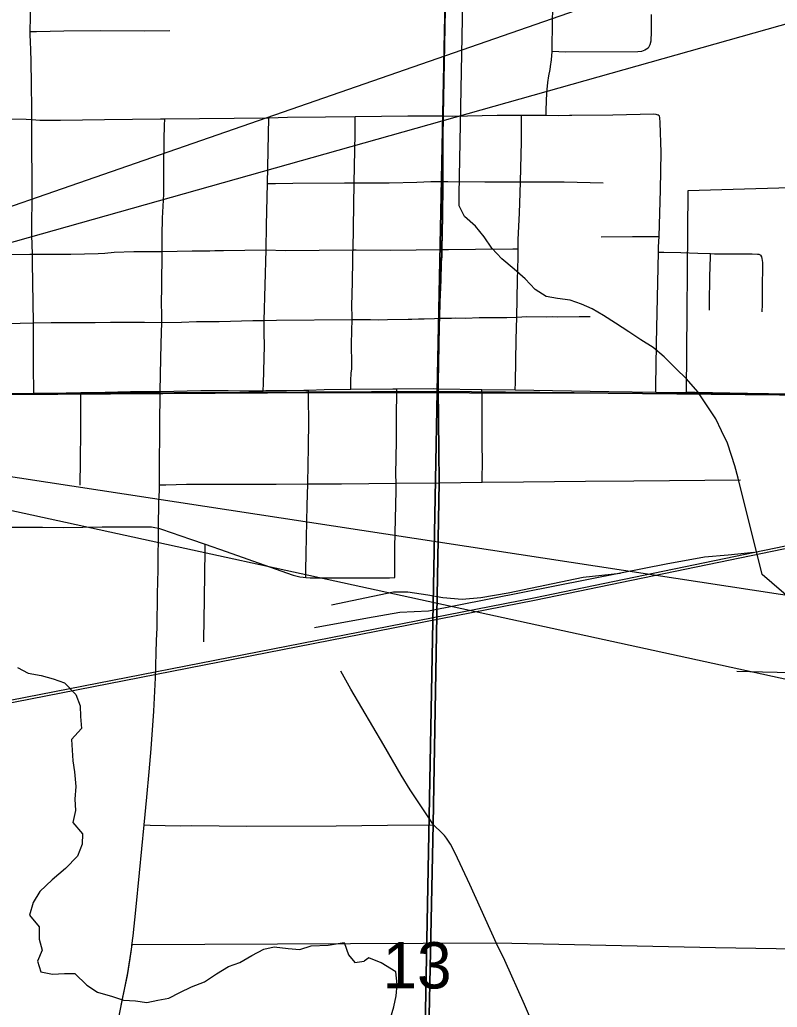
# Model space of a CAD drawing. Extents: x 0 to 42, y 0 to 22.
# Drawn here: x 5.866 to 6.55, y 16.928 to 17.821 of the extents above; entities that cross this region are included whole.
import ezdxf

# ---------------------------------------------------------------- set-up
doc = ezdxf.new("R2010")
doc.units = 0
for name, color, linetype in [('GM_X_City_Street', 7, 'Continuous'), ('GM_X_Corporation', 7, 'Continuous'), ('GM_X_County_Road', 7, 'Continuous'), ('GM_X_Interchange_Ramps', 7, 'Continuous'), ('GM_X_Minor_River', 7, 'Continuous'), ('GM_X_Rail_Line', 7, 'Continuous'), ('GM_X_Section', 7, 'Continuous'), ('GM_X_Section_Text', 7, 'Continuous'), ('GM_X_State_Route', 7, 'Continuous'), ('GM_X_Township_Road', 7, 'Continuous'), ('GM_X_US_Route', 7, 'Continuous'), ('SH_Text', 7, 'Continuous')]:
    doc.layers.add(name, color=color, linetype=linetype)

msp = doc.modelspace()

# ---------------------------------------------------------------- linework, layer by layer
at = {"layer": 'GM_X_City_Street'}
for points in [[(6.34097, 17.73431), (6.34111, 17.7391), (6.34158, 17.75455), (6.34246, 17.76377), (6.34333, 17.7699), (6.34449, 17.77544), (6.345, 17.77838), (6.34572, 17.78441), (6.34643, 17.79185), (6.34629, 17.79669), (6.34689, 17.83399)], [(6.43596, 17.82527), (6.43596, 17.81905), (6.43583, 17.80656), (6.43551, 17.8044), (6.43544, 17.8012), (6.43475, 17.79791), (6.43297, 17.79498), (6.43022, 17.79295), (6.42701, 17.79196), (6.42377, 17.79168), (6.35856, 17.79118), (6.34643, 17.79185)], [(5.87522, 17.80991), (5.88086, 17.81), (5.90558, 17.81039), (5.93845, 17.81086), (5.9782, 17.81048), (6.0012, 17.81076)], [(5.84436, 17.73109), (5.87161, 17.7307), (5.87651, 17.7304), (5.88395, 17.72993), (5.90253, 17.72994), (5.94208, 17.73047), (5.99277, 17.73097), (5.99668, 17.73107), (6.09066, 17.73191), (6.10755, 17.73248), (6.1417, 17.73291), (6.16845, 17.73321), (6.21606, 17.73374), (6.24832, 17.73358), (6.25639, 17.73354), (6.29675, 17.73419), (6.31888, 17.73427), (6.33992, 17.73434), (6.34097, 17.73431), (6.35176, 17.73406), (6.36217, 17.73424), (6.3643, 17.73425), (6.40115, 17.73451), (6.42597, 17.73527), (6.43823, 17.73538), (6.4401, 17.73528), (6.44173, 17.73463)], [(6.3131, 17.48612), (6.31324, 17.49269), (6.31402, 17.53152), (6.31449, 17.55198), (6.31525, 17.5852), (6.3157, 17.60589), (6.31565, 17.61351), (6.31559, 17.62169), (6.31597, 17.628), (6.31681, 17.6459), (6.31745, 17.66427), (6.31774, 17.67421), (6.31882, 17.71056), (6.31886, 17.72908), (6.31888, 17.73427)], [(6.43989, 17.48408), (6.44004, 17.49163), (6.44036, 17.50704), (6.44049, 17.52845), (6.44243, 17.61068), (6.44255, 17.6154), (6.44303, 17.62484), (6.44431, 17.66681), (6.44484, 17.70075), (6.44387, 17.72739), (6.44365, 17.73224), (6.44341, 17.73327), (6.44173, 17.73463)], [(5.99238, 17.48465), (5.99281, 17.50001), (5.99343, 17.52793), (5.99389, 17.54707), (5.99392, 17.55733), (5.99353, 17.56155), (5.99374, 17.56422), (5.99387, 17.5794), (5.99422, 17.61131), (5.99438, 17.62585), (5.99464, 17.64136), (5.99572, 17.66288), (5.99585, 17.68767), (5.99617, 17.71266), (5.99651, 17.725), (5.99668, 17.73107)], [(6.08554, 17.48544), (6.08571, 17.49206), (6.08658, 17.52586), (6.08634, 17.53755), (6.08651, 17.54886), (6.08812, 17.61255), (6.08863, 17.63504), (6.08928, 17.67252), (6.09066, 17.73191)], [(6.16456, 17.48684), (6.16476, 17.49422), (6.16497, 17.50169), (6.16547, 17.50488), (6.1654, 17.5095), (6.16535, 17.52733), (6.16568, 17.53951), (6.16578, 17.54971), (6.16561, 17.56421), (6.16587, 17.57038), (6.16637, 17.60132), (6.16647, 17.6105), (6.16664, 17.6127), (6.16772, 17.6731), (6.16851, 17.71752), (6.16848, 17.72685), (6.16845, 17.73321)], [(6.08928, 17.67252), (6.09651, 17.67267), (6.11216, 17.67299), (6.15898, 17.67305), (6.16772, 17.6731), (6.19922, 17.67326), (6.2242, 17.67386), (6.23675, 17.67429), (6.24789, 17.67434), (6.25233, 17.67436), (6.28561, 17.67409), (6.31339, 17.67419), (6.31774, 17.67421), (6.3572, 17.67406), (6.3925, 17.67316)], [(6.39074, 17.62452), (6.4189, 17.6247), (6.44303, 17.62484)], [(5.80359, 17.60771), (5.8747, 17.60878), (5.87712, 17.60878), (5.9119, 17.60875), (5.93653, 17.60943), (5.94249, 17.60976), (5.95105, 17.61069), (5.96855, 17.61124), (5.98998, 17.61121), (5.99422, 17.61131), (6.02137, 17.61191), (6.03735, 17.61185), (6.04179, 17.61201), (6.04959, 17.61196), (6.08812, 17.61255), (6.10531, 17.61211), (6.16664, 17.6127), (6.16946, 17.61276), (6.20011, 17.6125), (6.24702, 17.613), (6.25269, 17.61306), (6.27725, 17.61318), (6.31103, 17.61347), (6.31565, 17.61351)], [(6.44243, 17.61068), (6.44722, 17.61061), (6.46247, 17.6104), (6.47801, 17.60976)], [(5.84202, 17.54583), (5.87796, 17.54665), (5.89419, 17.54702), (5.91537, 17.54697), (5.93367, 17.54714), (5.94766, 17.5473), (5.96643, 17.54747), (5.97842, 17.54732), (5.99389, 17.54707), (6.01169, 17.54736), (6.02517, 17.54785), (6.04576, 17.54799), (6.07604, 17.5487), (6.08651, 17.54886), (6.09762, 17.54903), (6.16578, 17.54971), (6.18227, 17.54965), (6.18979, 17.54955), (6.19783, 17.5498), (6.21649, 17.54991), (6.2198, 17.54999), (6.22566, 17.55045), (6.23076, 17.55042), (6.24016, 17.55076), (6.24478, 17.55085), (6.25124, 17.55093), (6.25539, 17.55099), (6.2588, 17.55127), (6.2681, 17.55108), (6.28042, 17.55161), (6.2907, 17.55163), (6.30561, 17.55162), (6.31449, 17.55198), (6.32361, 17.55234), (6.34117, 17.55214), (6.34663, 17.55232), (6.35131, 17.55217), (6.37067, 17.55245), (6.38065, 17.55253)], [(6.12396, 17.31674), (6.12408, 17.32309), (6.12435, 17.33837), (6.12515, 17.38167), (6.12571, 17.40116), (6.12621, 17.4188), (6.12639, 17.43389), (6.12656, 17.45878), (6.12637, 17.47683), (6.12639, 17.48268), (6.12639, 17.48604)], [(6.20436, 17.31657), (6.20449, 17.33136), (6.20451, 17.34376), (6.20558, 17.39517), (6.20549, 17.40178), (6.20539, 17.40994), (6.2058, 17.43989), (6.20579, 17.46746), (6.20603, 17.47925), (6.20618, 17.48719)], [(6.28328, 17.40266), (6.28337, 17.40856), (6.28351, 17.41802), (6.28308, 17.44022), (6.28315, 17.45287), (6.28308, 17.48153), (6.28307, 17.48661)], [(5.92018, 17.40007), (5.9206, 17.42192), (5.9207, 17.44908), (5.9207, 17.47651), (5.9207, 17.48375)], [(5.99182, 17.40032), (5.99765, 17.40046), (6.01629, 17.40088), (6.04735, 17.40085), (6.09706, 17.40111), (6.12571, 17.40116), (6.15609, 17.40122), (6.20549, 17.40178), (6.24457, 17.40222), (6.28328, 17.40266), (6.32068, 17.40308), (6.37661, 17.40376), (6.4201, 17.4039), (6.51643, 17.40484)], [(5.85831, 17.3621), (5.88618, 17.36209), (5.90512, 17.36188), (5.94001, 17.36235), (5.97854, 17.36252), (5.98465, 17.36231), (5.98764, 17.36192), (5.99096, 17.36119), (5.99354, 17.36043), (6.01996, 17.35127), (6.03313, 17.34674), (6.0522, 17.34018), (6.07174, 17.33329), (6.08594, 17.32809), (6.11247, 17.31893), (6.1186, 17.31737), (6.12173, 17.31686), (6.12396, 17.31674), (6.12803, 17.31652), (6.15295, 17.31632), (6.18716, 17.3163), (6.19959, 17.3165), (6.20436, 17.31657)], [(6.03193, 17.2587), (6.0319, 17.26177), (6.03227, 17.27708), (6.03285, 17.31963), (6.03307, 17.34098), (6.03313, 17.34674)], [(6.2393, 17.09333), (6.23024, 17.1069), (6.2181, 17.12497), (6.20994, 17.13821), (6.19433, 17.16507), (6.16468, 17.21578), (6.15564, 17.23209)], [(6.51313, 17.23195), (6.53637, 17.23139), (6.58918, 17.23021), (6.6482, 17.22886), (6.73817, 17.22711), (6.95882, 17.22428), (7.12353, 17.22224), (7.19806, 17.2209), (7.22604, 17.22089), (7.23651, 17.22085), (7.23844, 17.22081), (7.28506, 17.22003), (7.33789, 17.21957), (7.35026, 17.21928), (7.35794, 17.2189)], [(5.978, 17.09313), (5.98352, 17.09303), (5.99684, 17.09253), (6.01078, 17.0922), (6.0207, 17.09273), (6.04583, 17.09231), (6.07077, 17.09198), (6.15137, 17.09246), (6.19788, 17.09304), (6.2393, 17.09333)]]:
    msp.add_lwpolyline(points, dxfattribs=at)
at = {"layer": 'GM_X_Corporation'}
for points in [[(6.72551, 17.67354), (6.46906, 17.66602), (6.46742, 17.48421), (6.47556, 17.48406), (6.66424, 17.48062)], [(7.47908, 16.96598), (6.49403, 16.98224), (6.29595, 16.98648), (5.9668, 16.98491), (5.9629, 16.9596), (5.95483, 16.91921), (5.94278, 16.86026), (5.94051, 16.84585), (5.93894, 16.83247), (5.9381, 16.82001), (5.9379, 16.80753), (5.93906, 16.78883), (5.94084, 16.77646), (5.94405, 16.76124), (5.72673, 16.76826), (5.73133, 16.9785), (5.22304, 16.97605), (5.22856, 17.19375), (5.2302, 17.32255), (4.7322, 17.32827)]]:
    msp.add_lwpolyline(points, dxfattribs=at)
at = {"layer": 'GM_X_County_Road'}
for points in [[(5.87522, 17.80991), (5.87525, 17.8231), (5.87508, 17.84761), (5.87471, 17.86251), (5.87475, 17.87179), (5.87442, 17.8966), (5.87424, 17.92141), (5.87373, 17.92765), (5.87404, 17.93295), (5.8741, 17.93587), (5.87375, 17.94813), (5.87373, 17.95546)], [(6.24832, 17.73358), (6.24995, 17.82919), (6.25082, 17.88206), (6.25103, 17.8962)], [(5.87651, 17.7304), (5.87645, 17.73736), (5.87617, 17.7649), (5.87579, 17.79575), (5.87545, 17.79824), (5.87522, 17.80928), (5.87522, 17.80991)], [(5.87712, 17.60878), (5.87666, 17.62598), (5.87663, 17.63179), (5.87683, 17.66218), (5.87701, 17.68807), (5.87673, 17.69423), (5.87658, 17.7159), (5.87651, 17.7304)], [(6.24789, 17.67434), (6.248, 17.71422), (6.24832, 17.73358)], [(6.24702, 17.613), (6.2476, 17.64331), (6.24786, 17.67105), (6.24789, 17.67434)], [(6.24478, 17.55085), (6.24513, 17.56481), (6.24606, 17.58472), (6.24645, 17.60131), (6.2467, 17.60422), (6.24711, 17.60643), (6.24698, 17.61193), (6.24702, 17.613)], [(5.87796, 17.54665), (5.87731, 17.60116), (5.87712, 17.60878)], [(5.87836, 17.4831), (5.87827, 17.49131), (5.87817, 17.4998), (5.87803, 17.51757), (5.87813, 17.5319), (5.87796, 17.54665)], [(6.24363, 17.48725), (6.24373, 17.49297), (6.2446, 17.54384), (6.24478, 17.55085)], [(6.29618, 16.98593), (6.27217, 17.03944), (6.25896, 17.06758), (6.25453, 17.07583), (6.25106, 17.08106), (6.24909, 17.08353), (6.24698, 17.08586), (6.2393, 17.09333)], [(6.4244, 16.65644), (6.40838, 16.71563), (6.40126, 16.73947), (6.39422, 16.76003), (6.38711, 16.7801), (6.37869, 16.80004), (6.36573, 16.82835), (6.34597, 16.87409), (6.32144, 16.93084), (6.30363, 16.97061), (6.29618, 16.98593)]]:
    msp.add_lwpolyline(points, dxfattribs=at)
at = {"layer": 'GM_X_Interchange_Ramps'}
for points in [[(6.22053, 16.21457), (6.23907, 17.09389), (6.24433, 17.40278), (6.2434, 17.4878), (6.2435, 17.49353), (6.24437, 17.5444), (6.24455, 17.55141), (6.2449, 17.56537), (6.24583, 17.58527), (6.24622, 17.60187), (6.24647, 17.60477), (6.24688, 17.60698), (6.24675, 17.61249), (6.24679, 17.61355), (6.24737, 17.64386), (6.24763, 17.67161), (6.24766, 17.6749), (6.24776, 17.71478), (6.24809, 17.73413), (6.24972, 17.82974)], [(6.24972, 17.82974), (6.24809, 17.73413), (6.24776, 17.71478), (6.24766, 17.6749), (6.24763, 17.67161), (6.24737, 17.64386), (6.24679, 17.61355), (6.24675, 17.61249), (6.24688, 17.60698), (6.24647, 17.60477), (6.24622, 17.60187), (6.24583, 17.58527), (6.2449, 17.56537), (6.24455, 17.55141), (6.24437, 17.5444), (6.2435, 17.49353), (6.2434, 17.4878), (6.24433, 17.40278), (6.23907, 17.09389), (6.22053, 16.21457)]]:
    msp.add_lwpolyline(points, dxfattribs=at)
at = {"layer": 'GM_X_Minor_River'}
for points in [[(6.26231, 17.66276), (6.27182, 18.15466)], [(6.51442, 17.40633), (6.51123, 17.4174), (6.50839, 17.42695), (6.50482, 17.43803), (6.49936, 17.44915), (6.49427, 17.45989), (6.48765, 17.46989), (6.4781, 17.48451), (6.46772, 17.49611), (6.45806, 17.50542), (6.44766, 17.51588), (6.4376, 17.52444), (6.42637, 17.5315), (6.41553, 17.53855), (6.40356, 17.54638), (6.39272, 17.55344), (6.38261, 17.55934), (6.37284, 17.56371), (6.36269, 17.56733), (6.35135, 17.5687), (6.34116, 17.57042), (6.33105, 17.5767), (6.32215, 17.58637), (6.3121, 17.59531), (6.30093, 17.60465), (6.29203, 17.61432), (6.28503, 17.62433), (6.27727, 17.63398), (6.26722, 17.64292), (6.26248, 17.6525), (6.26231, 17.66276), (6.26193, 17.66276)], [(6.72436, 17.0285), (6.72652, 17.09945), (6.67481, 17.14681), (6.65151, 17.1564), (6.62225, 17.209), (6.62062, 17.2227), (6.60435, 17.22341), (6.60359, 17.26139), (6.53617, 17.31932), (6.51442, 17.40633)], [(5.8635, 17.23532), (5.87325, 17.23017), (5.88496, 17.22801), (5.8959, 17.22511), (5.90605, 17.22146), (5.91643, 17.21098), (5.92036, 17.20065), (5.92052, 17.19115), (5.9214, 17.18013), (5.91245, 17.17046), (5.91298, 17.16058), (5.91352, 17.15108), (5.91519, 17.14117), (5.9164, 17.12786), (5.91537, 17.1165), (5.91589, 17.10624), (5.91374, 17.09528), (5.92223, 17.08522), (5.92201, 17.07574), (5.91796, 17.06482), (5.90708, 17.05368), (5.89509, 17.0437), (5.88383, 17.03295), (5.87792, 17.02321), (5.87461, 17.01152), (5.8831, 17.00108), (5.88322, 16.99007), (5.88602, 16.98014), (5.88161, 16.96999), (5.88481, 16.96043), (5.89538, 16.9583), (5.90602, 16.95882), (5.91551, 16.95899), (5.92626, 16.9485), (5.93598, 16.94221), (5.94954, 16.93811), (5.95933, 16.93485), (5.97033, 16.93423), (5.98054, 16.93286), (5.99045, 16.93492), (6.00035, 16.93659), (6.01033, 16.94168)], [(6.01033, 16.94168), (6.02069, 16.94676), (6.03257, 16.95143), (6.04336, 16.95878), (6.05414, 16.96537), (6.06446, 16.96894), (6.07523, 16.97515), (6.08599, 16.98098), (6.09552, 16.98305), (6.10801, 16.98163), (6.11861, 16.98063), (6.12893, 16.98382), (6.14412, 16.98462), (6.15859, 16.98695), (6.16251, 16.97586), (6.16829, 16.96895), (6.17668, 16.97004)], [(6.17138, 16.82512), (6.18245, 16.82908), (6.1931, 16.83152), (6.20342, 16.83587), (6.21307, 16.84479), (6.21783, 16.8557), (6.21576, 16.86599), (6.21293, 16.8763), (6.20518, 16.88671), (6.2016, 16.89703), (6.19876, 16.90696), (6.20051, 16.91869), (6.20336, 16.92888), (6.20545, 16.93871), (6.20641, 16.94895), (6.20512, 16.96036), (6.19203, 16.9686), (6.18075, 16.973), (6.17668, 16.97004)]]:
    msp.add_lwpolyline(points, dxfattribs=at)
at = {"layer": 'GM_X_Rail_Line'}
for points in [[(4.47383, 16.94433), (5.29105, 17.10831), (5.35214, 17.15863), (5.39526, 17.21015), (5.44676, 17.27605), (5.4779, 17.33236), (5.53419, 17.39227), (5.58929, 17.44738), (5.61803, 17.46895), (5.66355, 17.48093), (6.13676, 17.48381), (6.54177, 17.48275), (6.74799, 17.47956), (7.15832, 17.47956), (7.64504, 17.57729), (8.67372, 17.78019), (8.9, 17.82478)], [(2.1, 16.45897), (2.21286, 16.48078), (2.54544, 16.54648), (3.21541, 16.6797), (3.86075, 16.8081), (4.47344, 16.92932), (4.96779, 17.02934), (5.66093, 17.16754), (6.33, 17.29837), (6.9548, 17.42747), (7.57225, 17.54947), (8.20539, 17.68135), (8.86245, 17.80985), (8.9, 17.81723)], [(2.1, 16.45669), (2.21226, 16.47839), (2.5452, 16.54335), (3.215, 16.67749), (3.8612, 16.80582), (4.4739, 16.92704), (4.96825, 17.02706), (5.66138, 17.16526), (6.33046, 17.2961), (6.95526, 17.42519), (7.57271, 17.5472), (8.20585, 17.67908), (8.8629, 17.80757), (8.9, 17.81486)], [(6.52838, 17.33935), (6.50541, 17.33698), (6.48396, 17.33518), (6.44949, 17.32869), (6.40824, 17.32052)], [(6.40824, 17.32052), (6.26072, 17.29129), (6.23491, 17.28635), (6.20884, 17.28494), (6.17979, 17.27989), (6.13187, 17.27117)], [(6.14716, 17.29195), (6.20329, 17.3036), (6.21609, 17.30385), (6.23407, 17.30094), (6.24759, 17.29857), (6.26513, 17.29705), (6.28195, 17.29846), (6.30668, 17.30281), (6.37441, 17.31688), (6.40824, 17.32052)]]:
    msp.add_lwpolyline(points, dxfattribs=at)
at = {"layer": 'GM_X_Section'}
for points in [[(5.25236, 18.48474), (6.26311, 18.48848), (6.24266, 17.48458), (5.23337, 17.47966)], [(6.26311, 18.48848), (7.24526, 18.48165), (7.23157, 17.47498), (6.24266, 17.48458)], [(6.24266, 17.48458), (6.22399, 16.49401), (5.69234, 16.47995), (5.21557, 16.47686), (5.23337, 17.47966)], [(6.24266, 17.48458), (7.23157, 17.47498), (7.22048, 16.46486), (6.22495, 16.48633), (6.22399, 16.49401)]]:
    msp.add_lwpolyline(points, close=True, dxfattribs=at)
at = {"layer": 'GM_X_State_Route'}
for p, q in [((6.24363, 17.48725), (6.28307, 17.48661)), ((6.28307, 17.48661), (6.3131, 17.48612)), ((5.86205, 17.48285), (5.87836, 17.4831)), ((6.43989, 17.48408), (6.46766, 17.48366))]:
    msp.add_line(p, q, dxfattribs=at)
for points in [[(5.9207, 17.48375), (5.93149, 17.48392), (5.96567, 17.48458), (5.99238, 17.48465)], [(5.98254, 17.14113), (5.98436, 17.16196), (5.98674, 17.1958), (5.98826, 17.2261), (5.98909, 17.25991), (5.98971, 17.27109), (5.9902, 17.30184), (5.99056, 17.32363), (5.99064, 17.33601), (5.99095, 17.35147), (5.99096, 17.36119), (5.99135, 17.38556), (5.99184, 17.39485), (5.99182, 17.40032), (5.99177, 17.41339), (5.99222, 17.45372), (5.99238, 17.48465)], [(5.99238, 17.48465), (6.02929, 17.48554), (6.05401, 17.48571), (6.07255, 17.48527), (6.08554, 17.48544)], [(6.08554, 17.48544), (6.08801, 17.48547), (6.09658, 17.48551)], [(6.09658, 17.48551), (6.10038, 17.48553), (6.10658, 17.4857), (6.12205, 17.48586), (6.12639, 17.48604)], [(6.12639, 17.48604), (6.14064, 17.48662), (6.16456, 17.48684)], [(6.16456, 17.48684), (6.20256, 17.48717), (6.20618, 17.48719)], [(6.20618, 17.48719), (6.23968, 17.48732), (6.24363, 17.48725)], [(6.3131, 17.48612), (6.39758, 17.48475), (6.43989, 17.48408)], [(6.46766, 17.48366), (6.4758, 17.4835), (6.51835, 17.48286), (6.66448, 17.48006), (6.68621, 17.48016), (6.7017, 17.48081), (6.71403, 17.48197), (6.72628, 17.48379), (6.72841, 17.48423)], [(5.87836, 17.4831), (5.89422, 17.48334), (5.9207, 17.48375)], [(5.9669, 16.98343), (5.96703, 16.98436), (5.96812, 16.99293), (5.97054, 17.0161), (5.97367, 17.05003), (5.978, 17.09313), (5.98054, 17.11832), (5.98254, 17.14113)], [(5.95885, 16.93743), (5.96282, 16.95718), (5.96541, 16.97247), (5.96649, 16.98065), (5.9669, 16.98343)], [(5.94428, 16.76068), (5.94351, 16.76366), (5.94108, 16.7759), (5.93929, 16.78827), (5.93849, 16.79761), (5.93813, 16.80697), (5.93833, 16.81946), (5.93917, 16.83191), (5.94059, 16.84431), (5.94301, 16.8597), (5.94657, 16.87805), (5.95547, 16.92063), (5.95885, 16.93743)]]:
    msp.add_lwpolyline(points, dxfattribs=at)
at = {"layer": 'GM_X_Township_Road'}
msp.add_line((6.47801, 17.60976), (6.48942, 17.6093), dxfattribs=at)
for points in [[(6.48853, 17.55809), (6.48852, 17.56414), (6.48889, 17.58838), (6.48935, 17.60655), (6.48942, 17.6093)], [(6.48942, 17.6093), (6.4931, 17.60915), (6.5271, 17.60891), (6.53184, 17.60881), (6.533, 17.60875), (6.53375, 17.60858), (6.53437, 17.60827), (6.53499, 17.60779)], [(6.53605, 17.55681), (6.53623, 17.56318), (6.53621, 17.57593), (6.53654, 17.60132), (6.53643, 17.60309), (6.53616, 17.60471), (6.53575, 17.60628), (6.53499, 17.60779)]]:
    msp.add_lwpolyline(points, dxfattribs=at)
at = {"layer": 'GM_X_US_Route'}
for p, q in [((6.24363, 17.48725), (6.28307, 17.48661)), ((6.28307, 17.48661), (6.3131, 17.48612)), ((5.86205, 17.48285), (5.87836, 17.4831)), ((6.43989, 17.48408), (6.46766, 17.48366))]:
    msp.add_line(p, q, dxfattribs=at)
for points in [[(5.9207, 17.48375), (5.93149, 17.48392), (5.96567, 17.48458), (5.99238, 17.48465)], [(5.99238, 17.48465), (6.02929, 17.48554), (6.05401, 17.48571), (6.07255, 17.48527), (6.08554, 17.48544)], [(6.08554, 17.48544), (6.08801, 17.48547), (6.09658, 17.48551)], [(6.09658, 17.48551), (6.10038, 17.48553), (6.10658, 17.4857), (6.12205, 17.48586), (6.12639, 17.48604)], [(6.12639, 17.48604), (6.14064, 17.48662), (6.16456, 17.48684)], [(6.16456, 17.48684), (6.20256, 17.48717), (6.20618, 17.48719)], [(6.20618, 17.48719), (6.23968, 17.48732), (6.24363, 17.48725)], [(6.3131, 17.48612), (6.39758, 17.48475), (6.43989, 17.48408)], [(6.46766, 17.48366), (6.4758, 17.4835), (6.51835, 17.48286), (6.66448, 17.48006), (6.68621, 17.48016), (6.7017, 17.48081), (6.71403, 17.48197), (6.72628, 17.48379), (6.72841, 17.48423)], [(5.87836, 17.4831), (5.89422, 17.48334), (5.9207, 17.48375)]]:
    msp.add_lwpolyline(points, dxfattribs=at)
at = {"layer": 'SH_Text'}
for points in [[(9.43895, 18.8951), (5.35897, 17.47865), (9.43895, 18.63003)], [(9.43895, 16.85993), (5.39257, 17.47874), (9.43895, 16.59708)]]:
    msp.add_lwpolyline(points, close=True, dxfattribs=at)

# ---------------------------------------------------------------- texts
at = {"layer": 'GM_X_Section_Text'}
msp.add_text('13', height=0.041856, rotation=0.00001, dxfattribs=at).set_placement((6.19328, 16.94542))

doc.saveas('drawing.dxf')
